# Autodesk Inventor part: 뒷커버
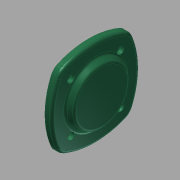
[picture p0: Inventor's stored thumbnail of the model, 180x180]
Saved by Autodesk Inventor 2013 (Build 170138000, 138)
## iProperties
Created: 2015-11
Part Number: 뒷커버
Material: 알루미늄 6061
Document SubType Name: Modeling
Designer: mduedu
Density: 2.71 g/cm^3
Mass: 325.353 g
Surface Area: 247.583 cm^2
Volume: 120.056 cm^3
Author: mduedu
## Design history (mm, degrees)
sketch "스케치1"
  geometry: L1 (50, 50)-(-50, 50); L2 (-50, 50)-(-50, -50); L3 (-50, -50)-(50, -50); L4 (50, -50)-(50, 50); L5 (0, 50)-(0, -50); L6 (50, 0)-(-50, 0); A1 r 90 centre (-40, 0) between (40.415, -40.415) and (40.415, 40.415); A2 r 90 centre (40, 0) between (-40.415, 40.415) and (-40.415, -40.415); A3 r 90 centre (0, -40) between (40.415, 40.415) and (-40.415, 40.415); A4 r 90 centre (0, 40) between (-40.415, -40.415) and (40.415, -40.415); 2 further points
  constraints: 12 end point, 8 point on circle, 5 midpoint, 4 centre point, 2 horizontal alignment, 2 parallel, 2 perpendicular, 2 symmetric about line, 2 tangent, 2 vertical alignment, 1 equal radius, 1 horizontal, 2 other
  dimensions: "d0" = 100 distance of L3.end L1.start; "d2" = 90 radius of A1
extrude "돌출1" new body sketch "스케치1" distance "d3" = 8; taper "d4" = 0 deg
sketch "스케치2"
  geometry: C1 r 35 at (0, 0); 1 further point
  constraints: 1 centre point, 1 coincident
  dimensions: "d5" = 70 diameter of C1
extrude "돌출2" join sketch "스케치2" distance "d6" = 7; taper "d7" = -30 deg
sketch "스케치3"
  geometry: L1 (0, 0)-(0, 40); L2 (0, 0)-(-28.284, 28.284); A1 r 40 centre (0, 0) between (0, 40) and (-28.284, 28.284); 2 further points
  constraints: 4 end point, 2 coincident, 2 point on circle, 1 centre point, 1 vertical
  dimensions: "d8" = 80 diameter of A1; "d9" = 45 deg angle of L1 L2
hole "구멍1" sketch "스케치3" at (-28.284, 28.284) diameter "d11" = 4.5; stored, may be unused: countersink angle "d15" = 90 deg, drill point angle "d17" = 118 deg; dims "d12" = 6, "d13" = 8, "d14" = 4.4, "d16" = 8
sketch "스케치4"
  geometry: C1 r 35 at (0, 0); 1 further point
  constraints: 1 centre point, 1 coincident
  dimensions: "d21" = 70 diameter of C1
extrude "돌출3" join sketch "스케치4" distance "d23" = 12; taper "d24" = 0 deg
hole "구멍2" diameter "d27" = 30; stored, may be unused: countersink angle "d31" = 90 deg, drill point angle "d33" = 0 deg; dims "d25" = 10, "d26" = 10, "d28" = 6, "d29" = 40, "d30" = 12, "d32" = 15
fillet "모깎기2" dims "d35" = 15
fillet "모깎기3" dims "d36" = 3
fillet "모깎기4" dims "d37" = 3
fillet "모깎기5" dims "d38" = 0.3
chamfer "모따기1" distance "d39" = 1; stored, may be unused: second distance "d40" = 2, angle "d41" = 45 deg
node "솔리드1"
pattern_circular "원형 패턴1" dims angle "d19" = 360 deg
